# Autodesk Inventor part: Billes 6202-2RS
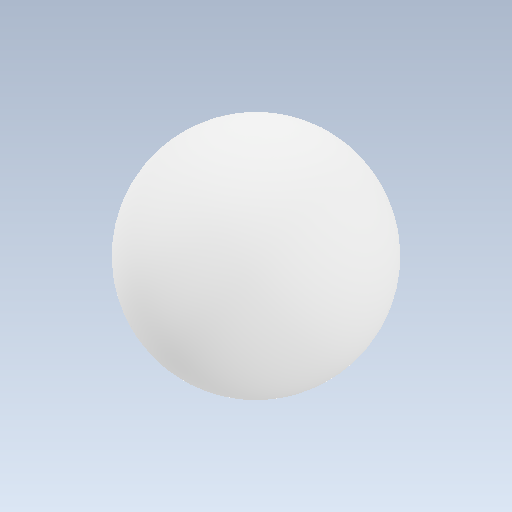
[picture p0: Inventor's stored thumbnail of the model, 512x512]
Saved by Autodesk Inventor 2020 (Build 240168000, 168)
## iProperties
Created: 2003-07
Part Number: Billes 6202-2RS
Material: Générique
Document SubType Name: Modeling
Designer: Bruno
Density: 1 g/cm^3
Appearance: Par défaut
Author: Bruno
Sending System: SolidWorks 2011
Last Author: frederic
Last Saved: 2012-02-20
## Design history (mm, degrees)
feature "Base-Révolution"
node "Solide1"
